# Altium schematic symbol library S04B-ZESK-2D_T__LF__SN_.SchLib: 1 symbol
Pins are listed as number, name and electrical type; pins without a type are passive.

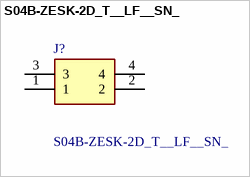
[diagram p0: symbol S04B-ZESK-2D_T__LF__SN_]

## S04B-ZESK-2D_T__LF__SN_
designator J?
CONN HEADER R/A 4POS 1.5MM; Manufacturer_Name: JST (JAPAN SOLDERLESS TERMINALS); Manufacturer_Part_Number: S04B-ZESK-2D(T)(LF)(SN); Geometry.Height: 6.3mm
footprint S04BZESK2DTLFSN
pins: 1, 2, 3, 4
